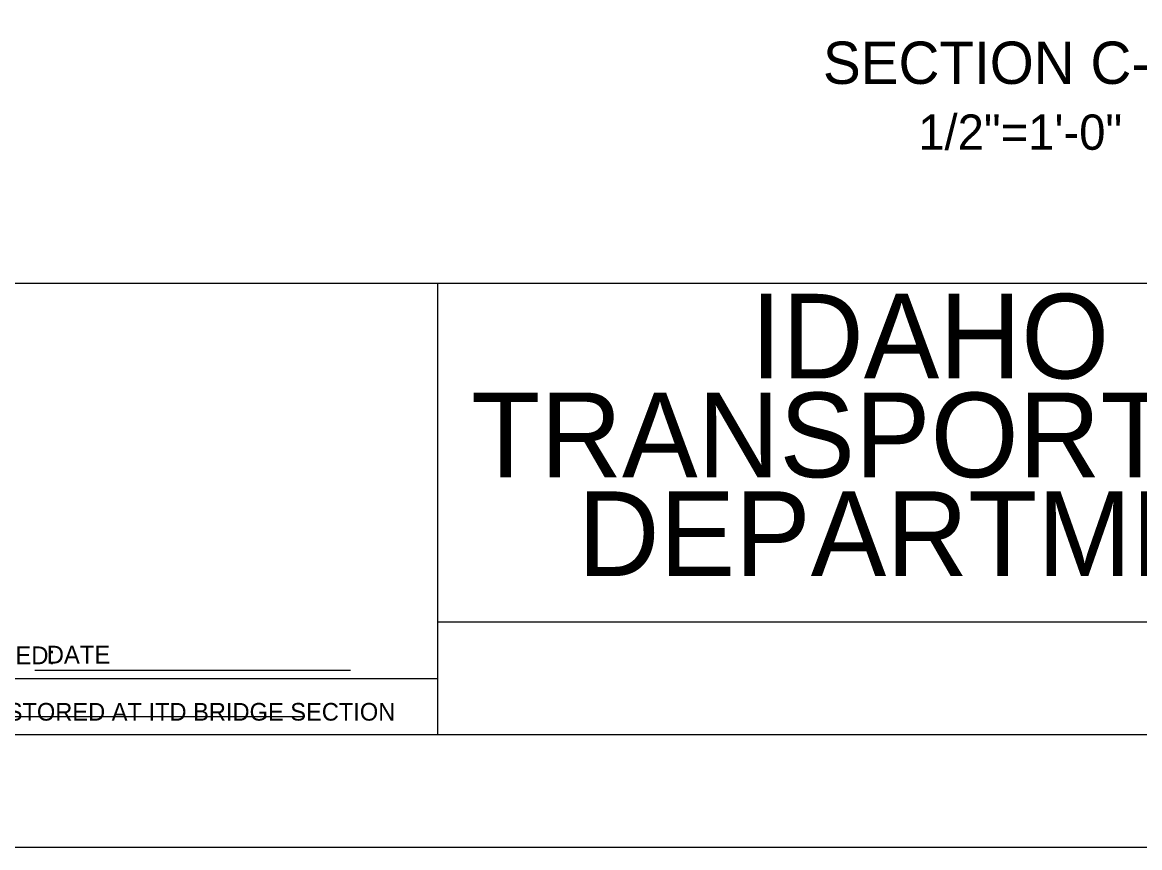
# Model space of a CAD drawing. Extents: x 0 to 68, y 0 to 47.1.
# Drawn here: x 24.32 to 34.21, y 0 to 7.31 of the extents above; entities that cross this region are included whole.
import ezdxf

# ---------------------------------------------------------------- set-up
doc = ezdxf.new("R2010")
doc.units = 0
for name, color, linetype in [('BORDER_ANNO_Cutsheet', 7, 'Continuous'), ('BRDG_ANNO_Anno-Large-Print', 7, 'Continuous'), ('BRDG_ANNO_Anno-Sheet', 7, 'Continuous'), ('BRDG_ANNO_Anno-Small-Print', 7, 'Continuous'), ('BRDG_ANNO_General-Notes', 7, 'Continuous')]:
    doc.layers.add(name, color=color, linetype=linetype)

msp = doc.modelspace()

# ---------------------------------------------------------------- linework, layer by layer
at = {"layer": 'BORDER_ANNO_Cutsheet'}
msp.add_lwpolyline([(0, 44), (68, 44), (68, 0), (0, 0)], close=True, dxfattribs=at)
at = {"layer": 'BRDG_ANNO_Anno-Large-Print'}
msp.add_line((23.7987, 1.1612), (26.8112, 1.1612), dxfattribs=at)
at = {"layer": 'BRDG_ANNO_Anno-Sheet'}
for p, q in [((3, 5), (38.5, 5)), ((28, 1), (28, 5)), ((28, 2), (38.5, 2))]:
    msp.add_line(p, q, dxfattribs=at)
msp.add_lwpolyline([(3, 43), (67, 43), (67, 1), (3, 1)], close=True, dxfattribs=at)
at = {"layer": 'BRDG_ANNO_Anno-Small-Print'}
for p, q in [((23, 1.5), (28, 1.5)), ((24.4325, 1.5725), (27.2273, 1.5725))]:
    msp.add_line(p, q, dxfattribs=at)

# ---------------------------------------------------------------- texts
at = {"layer": 'BRDG_ANNO_Anno-Sheet'}
for s, p in [('IDAHO', (30.7675, 4.1562)), ('TRANSPORTATION', (28.2937, 3.2812)), ('DEPARTMENT', (29.2387, 2.4062))]:
    msp.add_text(s, height=0.75, dxfattribs=at).set_placement(p)
at = {"layer": 'BRDG_ANNO_Anno-Small-Print'}
for s, height, p in [('DATE SIGNED:', 0.1575, (23.125, 1.625)), ('DATE', 0.15744, (24.5375, 1.6312)), ('ORIGINAL STORED AT ITD BRIDGE SECTION', 0.156433, (23.125, 1.1255))]:
    msp.add_text(s, height=height, dxfattribs=at).set_placement(p)
at = {"layer": 'BRDG_ANNO_General-Notes'}
for s, height, p in [('SECTION C-C', 0.375, (31.409, 6.7655)), ('1/2"=1\'-0"', 0.3125, (32.253, 6.1822))]:
    msp.add_text(s, height=height, dxfattribs=at).set_placement(p)

doc.saveas('drawing.dxf')
